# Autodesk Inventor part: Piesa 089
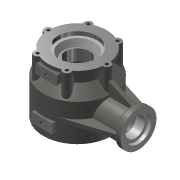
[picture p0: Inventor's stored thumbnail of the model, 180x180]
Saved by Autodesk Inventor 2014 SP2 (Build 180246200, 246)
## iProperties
Created: 2009-02
Part Number: Piesa 089
Document SubType Name: Modeling
Designer: Costel
Material: Steel, Cast
Density: 7.85 g/cm^3
Appearance: Steel - Cast
Mass: 4979.18 g
Surface Area: 1676.69 cm^2
Volume: 634.29 cm^3
Author: Costel
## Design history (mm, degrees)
sketch "Sketch2"
  geometry: L1 (40, 123)-(60, 123); L2 (60, 123)-(60, 116); L3 (60, 116)-(50, 116); L4 (50, 116)-(50, 95); L5 (50, 95)-(70, 75); L6 (70, 75)-(70, 0); L7 (70, 0)-(60, 0); L8 (60, 0)-(60, 3); L9 (60, 3)-(55, 3); L10 (55, 3)-(55, 10); L11 (55, 10)-(63, 10); L12 (63, 10)-(63, 72.101); L13 (63, 72.101)-(43, 92.101); L14 (43, 92.101)-(43, 103.89); L15 (37.259, 105.11)-(32, 93.298); L16 (32, 93.298)-(32, 80); L17 (32, 80)-(25, 80); L18 (25, 80)-(25, 103); L19 (25, 103)-(28.657, 103); L20 (28.657, 103)-(34, 115); L21 (34, 115)-(40, 115); L22 (40, 115)-(40, 123); L23 (74.5, 0)-(11.5, 0) reference; L24 (0, -12.3)-(0, 159.9) reference; A1 r 3 centre (40, 103.89) between (43, 103.89) and (37.259, 105.11)
  constraints: 44 end point, 17 parallel, 2 collinear, 2 point on circle, 2 tangent, 1 centre point, 1 horizontal, 1 perpendicular
  dimensions: "d0" = 120 diameter of L2 L24; "d1" = 140 diameter of L6 L24; "d2" = 126 diameter of L12 L24; "d3" = 120 diameter of L8 L24; "d4" = 110 diameter of L10 L24; "d5" = 3 distance between parallel lines of L23 L9; "d6" = 10 distance between parallel lines of L23 L11; "d7" = 123 distance between parallel lines of L23 L1; "d8" = 8 distance between parallel lines of L1 L21; "d9" = 3 radius of A1; "d10" = 24 deg angle of L15 L14; "d11" = 50 diameter of L18 L24; "d12" = 80 diameter of L22 L24; "d13" = 68 diameter of L20.end L24; "d14" = 43 distance between parallel lines of L1 L17; "d15" = 75 distance of L5.end L6.end; "d16" = 95 distance from line of L7 L4.end; "d17" = 86 diameter of L14 L24; "d18" = 64 diameter of L16 L24; "d19" = 45 deg angle of L23 L13; "d20" = 7 distance between parallel lines of L15 L20; "d21" = 7 distance between parallel lines of L13 L5; "d22" = 23 distance between parallel lines of L17 L19; "d23" = 7 distance between parallel lines of L1 L3
revolve "Revolution1" sketch "Sketch2" stored, may be unused: angle "d24" = 90 deg
workplane "Work Plane1"
sketch "Sketch3"
  geometry: L1 (0, -12.3)-(0, 159.9) reference; L2 (-84, 0)-(112, 0) reference; C1 r 31.5 at (0, 40)
  constraints: 1 centre point, 1 point on line
  dimensions: "d26" = 40 distance from line of L2 C1.centre; "d27" = 63 diameter of C1
extrude "Extrusion1" join sketch "Sketch3" stored distance "d28" = 10; taper "d29" = 0 deg
sketch "Sketch4"
  geometry: L1 (-125, 71.5)-(-70, 71.5) reference; L2 (-125, 8.5)-(-125, 71.5) reference; L3 (-125, 71.5)-(-109.5, 71.5); L4 (-109.5, 71.5)-(-115, 77); L5 (-115, 77)-(-125, 77); L6 (-125, 77)-(-125, 71.5); L7 (-63, 10)-(-63, 72.101) reference; L8 (-125, 40)-(-63, 40)
  constraints: 10 end point, 2 point on line, 1 collinear, 1 horizontal, 1 midpoint, 1 parallel, 1 perpendicular
  dimensions: "d30" = 10 distance of L4.end L5.end; "d31" = 15.5 distance from line of L6 L3.end; "d32" = 74 diameter of L5 L8
revolve "Revolution2" sketch "Sketch4" stored, may be unused: angle "d33" = 90 deg
sketch "Sketch5"
  geometry: L1 (-89.5, 0)-(183.5, 0) reference; L2 (0, -84)-(0, 112) reference; L3 (-60, -8)-(-49.356, -8); L4 (-60, 8)-(-49.356, 8); C1 r 50 at (0, 0) reference; C2 r 50 at (0, 0) reference; A1 r 8 centre (-60, 0) between (-59.467, 7.982) and (-59.467, -7.982); A2 r 50 centre (0, 0) between (-49.356, 8) and (-49.356, -8)
  constraints: 6 point on circle, 4 end point, 2 centre point, 2 concentric, 2 tangent, 1 horizontal, 1 parallel, 1 point on line
  dimensions: "d34" = 60 distance from line of L2 A1.centre; "d35" = 8 radius of A1
extrude "Extrusion2" join sketch "Sketch5" stored distance "d39" = 10; taper "d40" = 0 deg
hole "Hole1" diameter "d43" = 6.647; stored, may be unused: countersink angle "d47" = 90 deg, drill point angle "d49" = 118 deg; dims "d44" = 16, "d45" = 4, "d46" = 2, "d48" = 20, "d105" = 10, "d106" = 10
pattern_circular "Circular Pattern1" dims angle "d51" = 360 deg
workplane "Work Plane2"
sketch "Sketch6"
  geometry: L1 (0, -12.3)-(0, 159.9) reference; L2 (19.5, 96)-(-19.5, 96); L3 (-22.5, 99)-(-22.5, 113); L4 (-19.5, 116)-(19.5, 116); L5 (22.5, 113)-(22.5, 99); L6 (-22.804, 116)-(22.804, 116) reference; A1 r 3 centre (19.5, 99) between (19.5, 96) and (22.5, 99); A2 r 3 centre (19.5, 113) between (22.5, 113) and (19.5, 116); A3 r 3 centre (-19.5, 99) between (-22.5, 99) and (-19.5, 96); A4 r 3 centre (-19.5, 113) between (-19.5, 116) and (-22.5, 113); 2 further points
  constraints: 8 end point, 8 point on circle, 8 tangent, 4 centre point, 4 point on line, 3 equal radius, 2 parallel, 1 collinear, 1 horizontal, 1 perpendicular, 1 other
  dimensions: "d54" = 45 distance of point (22.5, 96) point (-22.5, 96); "d56" = 3 radius of A1; "d58" = 20 distance between parallel lines of L2 L4
extrude "Extrusion3" join sketch "Sketch6" stored distance "d59" = 10; taper "d60" = 0 deg
workplane "Work Plane3"
sketch "Sketch7"
  geometry: L1 (89.5, 0)-(-183.5, 0) reference; L2 (0, -12.3)-(0, 159.9) reference; L3 (22.5, 35)-(-22.5, 35); L4 (-22.5, 35)-(-22.5, 15); L5 (-22.5, 15)-(22.5, 15); L6 (22.5, 15)-(22.5, 35); L7 (22.5, 25)-(-22.5, 25)
  constraints: 10 end point, 2 midpoint, 2 parallel, 1 horizontal, 1 perpendicular, 1 other
  dimensions: "d62" = 45 distance between parallel lines of L4 L6; "d63" = 20 distance between parallel lines of L5 L3; "d64" = 25 distance between parallel lines of L1 L7
extrude "Extrusion4" join sketch "Sketch7" stored distance "d65" = 10; taper "d66" = 0 deg
fillet "Fillet1" dims "d67" = 3
hole "Hole2" diameter "d70" = 6.647; stored, may be unused: countersink angle "d74" = 90 deg, drill point angle "d76" = 118 deg; dims "d68" = 22.5, "d69" = 10, "d71" = 6, "d72" = 4, "d73" = 2, "d75" = 15
hole "Hole3" diameter "d79" = 6.647; stored, may be unused: countersink angle "d83" = 90 deg, drill point angle "d85" = 118 deg; dims "d77" = 22.5, "d78" = 10, "d80" = 6, "d81" = 4, "d82" = 2, "d84" = 15
sketch "Sketch8"
  geometry: L1 (-125, 3)-(-125, 77) reference; L2 (-118, 60)-(-118, 66.5); L3 (-118, 66.5)-(-125, 66.5); L4 (-125, 66.5)-(-125, 40); L5 (-118, 60)-(-100, 60); L6 (-100, 65.5)-(-78, 65.5); L7 (-78, 65.5)-(-78, 61.5); L8 (-100, 60)-(-100, 65.5); L9 (0, 61.5)-(-78, 61.5); L10 (0, 40)-(-125, 40); L11 (0, 61.5)-(0, 40)
  constraints: 20 end point, 3 perpendicular, 2 horizontal, 2 parallel, 1 midpoint
  dimensions: "d86" = 53 diameter of L3 L10; "d87" = 40 diameter of L5 L10; "d88" = 51 diameter of L6 L10; "d89" = 43 diameter of L9 L10; "d90" = 7 distance between parallel lines of L1 L2; "d91" = 18 distance between parallel lines of L2 L8; "d92" = 22 distance between parallel lines of L8 L7; "d107" = 125 distance between parallel lines of L11 L1
revolve "Revolution3" sketch "Sketch8" stored, may be unused: angle "d93" = 90 deg
sketch "Sketch9"
  geometry: L1 (-68, 123)-(-60, 123) reference; L2 (-68, 123)-(-68, 77) reference; L3 (-125, 77)-(-115, 77) reference; L4 (-115, 77)-(-109.5, 71.5) reference; L5 (-115, 77)-(-68, 97.926)
  constraints: 2 end point, 1 point on line
  dimensions: "d94" = 24 deg angle of L3 L5
feature "Rib1" sketch "Sketch9" dims "d95" = 1, "d96" = 8
sketch "Sketch10"
  geometry: L1 (-115, -37)-(-115, 37) reference; L2 (109, 0)-(-164, 0) reference; L3 (-69.886, 4)-(-115, 4); L4 (-69.886, -4)-(-115, -4); L5 (-115, 4)-(-115, -4); A1 r 70 centre (0, 0) between (-69.886, 4) and (-69.886, -4); 3 further points
  constraints: 6 end point, 2 point on circle, 2 symmetric about line, 1 centre point, 1 collinear, 1 perpendicular, 1 point on line, 3 other
  dimensions: "d97" = 8 distance between parallel lines of L4 L3
extrude "Extrusion5" join sketch "Sketch10" stored distance "d98" = 10; taper "d99" = 0 deg
sketch "Sketch11"
  geometry: L1 (-69.886, 0)-(-69.886, 8.755) reference; L2 (-125, 3)-(-115, 3) reference; L3 (-115, 3)-(-69.886, 0); L4 (-69.886, 0)-(-115, 0); L5 (-115, 3)-(-115, 0)
  constraints: 6 end point, 1 parallel, 1 perpendicular
extrude "Extrusion6" cut sketch "Sketch11" stored distance "d100" = 10; taper "d101" = 0 deg
workaxis "Work Axis1"
workplane "Work Plane4"
sketch "Sketch12"
  geometry: L1 (0.5, 31.5)-(-46.488, 31.5) reference; L2 (6, 37)-(0.5, 31.5) reference; L3 (6, 37)-(-87.862, 66.732); A1 r 70 centre (-109, 0) between (-39.114, 4) and (-39.114, -4) reference
  constraints: 2 end point, 1 point on circle, 1 tangent
feature "Rib2" sketch "Sketch12" dims "d103" = 1, "d104" = 8
mirror "Mirror1"
body "Solid1"
node "Projected Loop1"
other parameters: "d25" = 125, "d53" = -64, "d61" = -74, "d102" = 0
